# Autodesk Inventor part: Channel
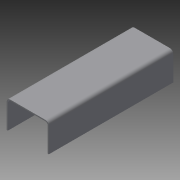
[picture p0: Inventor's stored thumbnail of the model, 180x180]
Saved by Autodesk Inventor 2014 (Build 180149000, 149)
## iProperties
Shininess: 64.0
Length Units: 11269
Angle Units: 11279
Time Units: 11290
Mass Units: 11283
Length Display Precision: 3
Angle Display Precision: 2
Compacted: True
Created: 2002-08
Part Number: Channel
Document SubType Name: Sheet Metal
Designer: t_munrn
Density: 1 g/cm^3
Sheet Metal Rule: Default
Material: Generic
Appearance: Default
Density: 0.0
Volumn: 0.0
Area: 0.0
PropertySet Name: Model Information
Control State: 0
Master: False
Checked Out: False
Author: t_munrn
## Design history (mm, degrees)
node "Contour Flange1"
  sketch "Sketch1"
    geometry: L1 (-112.5, -150)-(-112.5, 0); L2 (-112.5, 0)-(112.5, 0); L3 (112.5, 0)-(112.5, -150); 2 further points
    constraints: 6 end point, 2 parallel, 1 coincident, 1 midpoint, 1 perpendicular, 1 vertical
    dimensions: "d0" = 225 distance of L1.end L2.end; "d1" = 150 distance of L1.start L1.end
body "Solid1"
face "Plate1" dims "d2" = 665, "d4" = 12 (= BendRadius), "d5" = 6, "Thickness" = 6, "MinimumRemnant" = 12 (= 2 x Thickness), "BendReliefWidth" = 6 (= Thickness)
bend "Bend1" dims "d3" = 12 (= BendRadius), "d4" = 12 (= BendRadius), "d5" = 6, "d6" = 6 (= BendReliefWidth), "d7" = 3 (= BendReliefDepth), "d8" = 12 (= MinimumRemnant), "SeamGap" = 0.01, "Thickness" = 6, "MinimumRemnant" = 12 (= 2 x Thickness), "BendReliefWidth" = 6 (= Thickness)
other parameters: "BendRadius" = 12 (= 2 x Thickness), "BendReliefDepth" = 3 (= 0.5 x Thickness), "CornerReliefSize" = 24 (= 4 x Thickness), "TransitionRadius" = 12 (= BendRadius), "JacobiRadiusSize" = 6 (= Thickness), "GapSize" = 6 (= Thickness)
